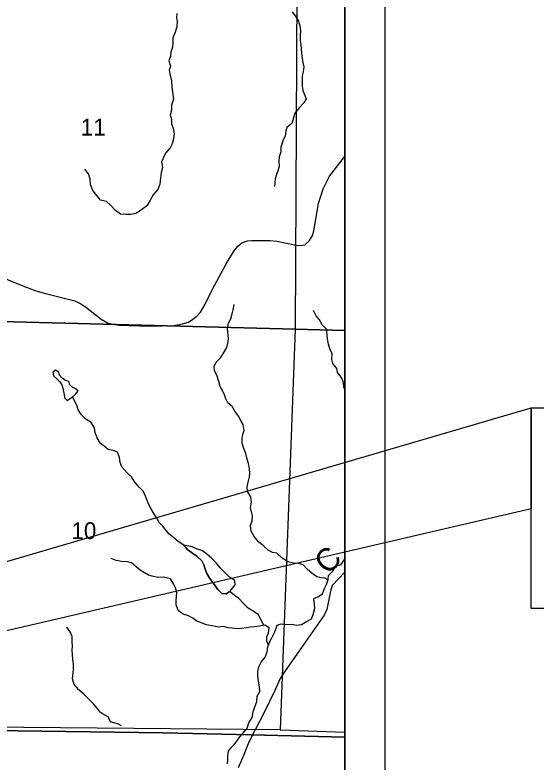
# Model space of a CAD drawing. Extents: x -7.1 to 34, y 0 to 22.
# Drawn here: x 8.077 to 9.377, y 17.646 to 19.508 of the extents above; entities that cross this region are included whole.
import ezdxf

# ---------------------------------------------------------------- set-up
doc = ezdxf.new("R2010")
doc.units = 0
for name, color, linetype in [('Default', 7, 'Continuous'), ('GM_X_County_Road', 7, 'Continuous'), ('GM_X_County_Road_Text', 7, 'Continuous'), ('GM_X_Minor_Lake', 7, 'Continuous'), ('GM_X_Minor_River', 7, 'Continuous'), ('GM_X_Section', 7, 'Continuous'), ('GM_X_Section_Text', 7, 'Continuous'), ('GM_X_State_Route', 7, 'Continuous'), ('GM_X_Township_Road', 7, 'Continuous'), ('SH_Cut_Line', 7, 'Continuous'), ('SH_Data', 7, 'Continuous'), ('SH_Text', 7, 'Continuous')]:
    doc.layers.add(name, color=color, linetype=linetype)

msp = doc.modelspace()

# ---------------------------------------------------------------- linework, layer by layer
at = {"layer": 'Default'}
for points in [[(8.9, 18.7216), (8.9, 19.7387), (8.7812, 19.7403), (8.7765, 18.7248)], [(8.9, 17.7202), (8.9, 18.7216), (8.7765, 18.7248), (8.739, 17.7258)]]:
    msp.add_lwpolyline(points, close=True, dxfattribs=at)
at = {"layer": 'GM_X_County_Road'}
msp.add_lwpolyline([(8.9, 18.1193), (8.869, 18.0861), (8.8643, 18.0716), (8.8606, 18.0512), (8.8551, 18.0259), (8.8488, 18.012), (8.8254, 17.979), (8.7848, 17.9203), (8.7514, 17.8728), (8.739, 17.8538), (8.7259, 17.8243), (8.6983, 17.7676), (8.6769, 17.7263)], dxfattribs=at)
at = {"layer": 'GM_X_Minor_Lake'}
for points in [[(8.1742, 18.6192), (8.1718, 18.6173), (8.1738, 18.6086), (8.1822, 18.6011), (8.1895, 18.5935), (8.1941, 18.586), (8.1964, 18.578), (8.1984, 18.5697), (8.2004, 18.5617), (8.2012, 18.5534), (8.2073, 18.547), (8.2209, 18.5566)], [(8.2209, 18.5566), (8.2296, 18.5639), (8.2352, 18.5711), (8.2272, 18.5768), (8.2215, 18.5798), (8.2142, 18.5858), (8.2115, 18.5945), (8.2031, 18.5967), (8.1951, 18.6027), (8.1882, 18.6102), (8.187, 18.6178), (8.1782, 18.6223), (8.1742, 18.6192)], [(8.4986, 18.1862), (8.5083, 18.175), (8.5209, 18.1653), (8.5313, 18.1591), (8.5432, 18.1475), (8.5483, 18.1377), (8.5522, 18.1268), (8.5558, 18.1155), (8.5636, 18.1034), (8.5733, 18.0903), (8.5837, 18.0757), (8.5934, 18.0656), (8.604, 18.0654), (8.613, 18.0713)], [(8.613, 18.0713), (8.6263, 18.0874), (8.6258, 18.0984), (8.6128, 18.1066), (8.6016, 18.1178), (8.5889, 18.1301), (8.5796, 18.1424), (8.5685, 18.1532), (8.555, 18.1648), (8.5435, 18.1729), (8.5306, 18.1769), (8.5191, 18.182), (8.4986, 18.1862)]]:
    msp.add_lwpolyline(points, dxfattribs=at)
at = {"layer": 'GM_X_Minor_River'}
for points in [[(8.4808, 19.512), (8.4802, 19.5017), (8.4823, 19.4919), (8.481, 19.4782), (8.4774, 19.4653), (8.4716, 19.4508), (8.4714, 19.4398), (8.4701, 19.428), (8.4666, 19.4154), (8.4652, 19.4056), (8.4616, 19.3934), (8.4653, 19.3805), (8.4624, 19.371), (8.4637, 19.3612), (8.4678, 19.3438), (8.4688, 19.3294), (8.4702, 19.3154), (8.4731, 19.2984), (8.4681, 19.2835), (8.4675, 19.271), (8.4647, 19.2584), (8.4679, 19.2486), (8.4677, 19.2357), (8.4717, 19.2259), (8.4742, 19.2119), (8.4729, 19.1994), (8.4697, 19.1865), (8.4646, 19.1769), (8.4531, 19.1638), (8.4472, 19.1512), (8.4432, 19.1413), (8.4457, 19.1277), (8.4422, 19.1151), (8.4405, 19.1022), (8.4391, 19.0866), (8.434, 19.0728)], [(8.7692, 19.5158), (8.7781, 19.5038), (8.7847, 19.4925), (8.7879, 19.4808), (8.7893, 19.4695), (8.7891, 19.4566), (8.7889, 19.4445), (8.7903, 19.4346), (8.7916, 19.4218), (8.793, 19.4059), (8.7959, 19.39), (8.7976, 19.379), (8.7963, 19.3676), (8.7935, 19.3554), (8.7939, 19.3308), (8.7952, 19.321), (8.8, 19.3089), (8.8036, 19.2987), (8.798, 19.2888), (8.7865, 19.2765), (8.7758, 19.2634), (8.7726, 19.2516), (8.7683, 19.2378), (8.7552, 19.2278), (8.7535, 19.2183), (8.7514, 19.2072), (8.7455, 19.1942), (8.7409, 19.1782), (8.7403, 19.1672), (8.7364, 19.1543), (8.7358, 19.1429), (8.7364, 19.1304), (8.7332, 19.1197), (8.7296, 19.1101), (8.7267, 19.0999), (8.7254, 19.09), (8.7248, 19.0805)], [(8.434, 19.0728), (8.4222, 19.0598), (8.4143, 19.0461), (8.4064, 19.0327), (8.3932, 19.0223), (8.3789, 19.0131), (8.3667, 19.0111), (8.3542, 19.0106), (8.3409, 19.0113), (8.3279, 19.0206), (8.3164, 19.0331), (8.3053, 19.0428), (8.2909, 19.0461), (8.2813, 19.0582), (8.272, 19.0703), (8.2662, 19.0854), (8.265, 19.0987), (8.2607, 19.1123), (8.2515, 19.1236)], [(8.8579, 18.0988), (8.8505, 18.1042), (8.841, 18.1048), (8.8308, 18.1073), (8.8185, 18.1154), (8.8062, 18.1266), (8.7962, 18.1374), (8.7848, 18.141), (8.7719, 18.1412), (8.7578, 18.1451), (8.7441, 18.1543), (8.7306, 18.1663), (8.72, 18.1684), (8.7093, 18.1739), (8.6982, 18.1839), (8.6847, 18.1951), (8.6743, 18.2078), (8.6669, 18.2213), (8.6651, 18.2353), (8.6695, 18.2468), (8.67, 18.2593), (8.6651, 18.2805), (8.6672, 18.2934), (8.6655, 18.3067), (8.6577, 18.3198), (8.6567, 18.332), (8.6595, 18.3434), (8.6624, 18.3564), (8.6637, 18.3662), (8.6628, 18.3769), (8.6599, 18.3897), (8.6563, 18.4006), (8.6531, 18.4146), (8.6483, 18.4271), (8.6443, 18.4407), (8.6445, 18.4521), (8.6462, 18.4627), (8.6491, 18.4722), (8.6465, 18.4874), (8.6407, 18.4975), (8.6348, 18.5084), (8.6259, 18.5208), (8.6189, 18.5321), (8.6082, 18.5414), (8.6035, 18.5515), (8.5999, 18.5613), (8.5948, 18.5719), (8.5893, 18.582), (8.5857, 18.5948), (8.5817, 18.6081), (8.5754, 18.6216), (8.5745, 18.6318), (8.5792, 18.6422), (8.5897, 18.653), (8.5978, 18.6652), (8.6059, 18.679), (8.6087, 18.6897), (8.61, 18.7007), (8.6086, 18.717), (8.6077, 18.7273), (8.6101, 18.7402), (8.6156, 18.7509), (8.6188, 18.7631), (8.6217, 18.7734), (8.6245, 18.7863)], [(8.9, 18.5745), (8.8975, 18.5801), (8.8969, 18.5918), (8.8921, 18.6046), (8.8821, 18.6166), (8.8804, 18.6272), (8.8707, 18.6396), (8.8675, 18.6494), (8.8688, 18.6638), (8.8637, 18.6736), (8.8597, 18.6872), (8.8568, 18.7004), (8.8559, 18.7103), (8.8549, 18.725), (8.8441, 18.7359), (8.8367, 18.7482), (8.8286, 18.7583), (8.8223, 18.7715)], [(8.4464, 18.2335), (8.4373, 18.2425), (8.4304, 18.2554), (8.4242, 18.2656), (8.4177, 18.2754), (8.4115, 18.2879), (8.4073, 18.2981), (8.4026, 18.3087), (8.3983, 18.3204), (8.3868, 18.3313), (8.3765, 18.3434), (8.3684, 18.3566), (8.3573, 18.3671), (8.3439, 18.3818), (8.34, 18.3928), (8.3384, 18.4053), (8.333, 18.4182), (8.3227, 18.4227), (8.3097, 18.4248), (8.3002, 18.4335), (8.2906, 18.4395), (8.2822, 18.4538), (8.2775, 18.4675), (8.2755, 18.4788), (8.2678, 18.4921), (8.2544, 18.5003), (8.2429, 18.512), (8.2349, 18.5237), (8.2313, 18.5358), (8.2209, 18.5566)], [(8.6979, 17.9866), (8.6902, 18.0024), (8.6847, 18.0129), (8.6717, 18.0218), (8.6591, 18.0292), (8.6475, 18.0411), (8.6352, 18.0546), (8.6252, 18.0612), (8.613, 18.0713), (8.604, 18.0654), (8.5934, 18.0656), (8.5837, 18.0757), (8.5733, 18.0903), (8.5636, 18.1034), (8.5558, 18.1155), (8.5522, 18.1268), (8.5483, 18.1377), (8.5432, 18.1475), (8.5313, 18.1591), (8.5209, 18.1653), (8.5083, 18.175), (8.4986, 18.1862), (8.4841, 18.1958), (8.4741, 18.2044), (8.4611, 18.2144), (8.4464, 18.2335)], [(8.4483, 18.107), (8.4335, 18.1058), (8.4198, 18.1091), (8.4103, 18.112), (8.4008, 18.1176), (8.3893, 18.124), (8.3794, 18.1326), (8.3679, 18.1424), (8.3576, 18.145), (8.3432, 18.146), (8.3299, 18.1485), (8.3173, 18.1534)], [(8.6534, 17.7265), (8.6565, 17.7305), (8.6604, 17.7438), (8.6689, 17.7569), (8.6713, 17.771), (8.6757, 17.7832), (8.6807, 17.7966), (8.6813, 17.8102), (8.6883, 17.8217), (8.6877, 17.8323), (8.6852, 17.8482), (8.6835, 17.8596), (8.6829, 17.8717), (8.6857, 17.8835), (8.6912, 17.895), (8.7016, 17.907), (8.7063, 17.9207), (8.7084, 17.9333), (8.7131, 17.9459), (8.7178, 17.9554), (8.7259, 17.9704), (8.7313, 17.9868), (8.7415, 17.9904), (8.7544, 17.9883), (8.7665, 17.9897), (8.7802, 17.9869), (8.7919, 17.989), (8.8046, 17.9964), (8.817, 18.0027), (8.821, 18.0137), (8.8253, 18.0294), (8.8243, 18.0392), (8.8233, 18.0532), (8.8331, 18.058), (8.8447, 18.0654), (8.8494, 18.0787), (8.8542, 18.0883), (8.8585, 18.1005), (8.8595, 18.1108), (8.8707, 18.122), (8.878, 18.1339), (8.8912, 18.1379), (8.899, 18.1502), (8.9, 18.1515)], [(8.7099, 17.9372), (8.7059, 17.9469), (8.7057, 17.9575), (8.7097, 17.9678), (8.7118, 17.98), (8.7003, 17.987), (8.6871, 17.9845), (8.675, 17.9828), (8.6648, 17.9818), (8.655, 17.9802), (8.6425, 17.9788), (8.6315, 17.9779), (8.6194, 17.9792), (8.6092, 17.9805), (8.5978, 17.9833), (8.5842, 17.9816), (8.5694, 17.9851), (8.5553, 17.9876), (8.5443, 17.9919), (8.5309, 17.997), (8.521, 18.0044), (8.5099, 18.0099), (8.4969, 18.0146), (8.4843, 18.0235), (8.4792, 18.0375), (8.4793, 18.0485), (8.4803, 18.0588), (8.4809, 18.0682), (8.4777, 18.08), (8.4726, 18.0897), (8.4656, 18.1025), (8.4483, 18.107)], [(8.3434, 17.7358), (8.3358, 17.74), (8.3161, 17.7463), (8.3099, 17.7587), (8.3, 17.7636), (8.29, 17.7703), (8.2824, 17.7801), (8.2728, 17.7915), (8.2498, 17.814), (8.2364, 17.8257), (8.2249, 17.8389), (8.221, 17.8533), (8.2224, 17.8673), (8.223, 17.8791), (8.2233, 17.8909), (8.2213, 17.9019), (8.2205, 17.9129), (8.2204, 17.9247), (8.2207, 17.9345), (8.2202, 17.9452), (8.2201, 17.9585), (8.2159, 17.9687), (8.207, 17.9819)], [(8.6534, 17.7265), (8.6374, 17.7084), (8.6233, 17.6884), (8.6161, 17.6808), (8.61, 17.6744), (8.6088, 17.6687), (8.6076, 17.6603), (8.6072, 17.6535), (8.6072, 17.6474), (8.6056, 17.6409)]]:
    msp.add_lwpolyline(points, dxfattribs=at)
at = {"layer": 'GM_X_Section'}
for points in [[(7.7801, 19.7571), (8.7812, 19.7403), (8.7765, 18.7248), (7.7545, 18.7512)], [(7.7545, 18.7512), (8.7765, 18.7248), (8.739, 17.7258), (7.7337, 17.7353)]]:
    msp.add_lwpolyline(points, close=True, dxfattribs=at)
at = {"layer": 'GM_X_State_Route'}
msp.add_lwpolyline([(8.0257, 18.8623), (8.0805, 18.8395), (8.1075, 18.8286), (8.1294, 18.8206), (8.1572, 18.8129), (8.1935, 18.804), (8.227, 18.7951), (8.242, 18.7879), (8.2535, 18.7808), (8.2925, 18.7495), (8.3081, 18.7408), (8.3195, 18.737), (8.3374, 18.7349), (8.3616, 18.7337), (8.4151, 18.732), (8.4738, 18.7339), (8.4957, 18.7379), (8.5102, 18.7426), (8.521, 18.7494), (8.531, 18.7576), (8.5398, 18.7671), (8.5516, 18.7874), (8.5705, 18.8245), (8.6072, 18.8938), (8.6256, 18.923), (8.633, 18.9317), (8.6388, 18.9371), (8.6435, 18.9398), (8.6496, 18.9428), (8.6576, 18.945), (8.6681, 18.9455), (8.687, 18.9457), (8.7129, 18.9461), (8.7306, 18.9441), (8.779, 18.9341), (8.7898, 18.9331), (8.8008, 18.9352), (8.8124, 18.9455), (8.82, 18.9584), (8.8227, 18.9699), (8.8342, 19.0383), (8.8463, 19.0746), (8.8621, 19.1067), (8.8877, 19.1396), (8.8999, 19.155), (8.9, 19.1551)], dxfattribs=at)
at = {"layer": 'GM_X_Township_Road'}
for points in [[(8.9, 17.7079), (8.9, 20.9), (6.7921, 20.9), (6.7882, 20.743), (6.7613, 19.7723), (6.7479, 19.0295), (6.7433, 18.7732), (6.7254, 18.1319), (6.7118, 17.7486), (7.7202, 17.7285), (8.4472, 17.7189), (8.6668, 17.7136)], [(6.633, 14.1), (8.9, 14.1), (8.9, 17.7079), (8.6668, 17.7136), (8.4472, 17.7189), (7.7202, 17.7285), (6.7118, 17.7486), (6.7058, 17.2839), (6.6822, 16.3488), (6.6748, 15.9993), (6.6586, 15.2372), (6.6565, 15.1357)]]:
    msp.add_lwpolyline(points, close=True, dxfattribs=at)
msp.add_lwpolyline([(8.6346, 17.6319), (8.643, 17.6511), (8.6506, 17.6686), (8.6561, 17.6821), (8.6618, 17.6959), (8.6679, 17.7086), (8.6731, 17.7192), (8.6769, 17.7263)], dxfattribs=at)
at = {"layer": 'SH_Cut_Line'}
for points in [[(8.9, 17.7079), (8.9, 20.9), (2.1, 20.9), (2.1, 17.7253), (2.5551, 17.7155), (2.7886, 17.7105), (3.0659, 17.6986), (3.7215, 17.6707), (3.8238, 17.6717), (3.8304, 17.7952), (4.3, 17.7873), (4.5657, 17.7857), (4.7094, 17.7848), (5.0443, 17.7832), (5.0544, 17.7831), (5.1115, 17.7819), (5.5047, 17.7737), (5.7514, 17.7685), (6.1904, 17.7592), (6.3575, 17.7557), (6.7118, 17.7486), (7.7202, 17.7285), (8.4472, 17.7189), (8.6668, 17.7136)], [(2.1, 17.7253), (2.1, 14.1), (8.9, 14.1), (8.9, 17.7079), (8.6668, 17.7136), (8.4472, 17.7189), (7.7202, 17.7285), (6.7118, 17.7486), (6.3575, 17.7557), (6.1904, 17.7592), (5.7514, 17.7685), (5.5047, 17.7737), (5.1115, 17.7819), (5.0544, 17.7831), (5.0443, 17.7832), (4.7094, 17.7848), (4.5657, 17.7857), (4.3, 17.7873), (3.8304, 17.7952), (3.8238, 17.6717), (3.7215, 17.6707), (3.0659, 17.6986), (2.7886, 17.7105), (2.5551, 17.7155)]]:
    msp.add_lwpolyline(points, close=True, dxfattribs=at)
at = {"layer": 'SH_Data'}
for p, q in [((9, 21), (9, 14)), ((8.9, 20.9), (8.9, 14.1))]:
    msp.add_line(p, q, dxfattribs=at)
at = {"layer": 'SH_Text'}
for points in [[(5.1887, 17.3067), (9.3652, 18.5286), (9.3652, 18.2766)], [(9.3652, 18.5286), (10.9993, 18.5286), (10.9993, 18.0286), (9.3652, 18.0286)]]:
    msp.add_lwpolyline(points, close=True, dxfattribs=at)

# ---------------------------------------------------------------- texts
at = {"layer": 'GM_X_County_Road_Text'}
msp.add_text('C', height=0.0568, rotation=45.2111, dxfattribs=at).set_placement((8.8584, 18.1105))
at = {"layer": 'GM_X_Section_Text'}
for s, p in [('11', (8.2415, 19.2074)), ('10', (8.2182, 18.2016))]:
    msp.add_text(s, height=0.04186, rotation=0, dxfattribs=at).set_placement(p)

doc.saveas('drawing.dxf')
